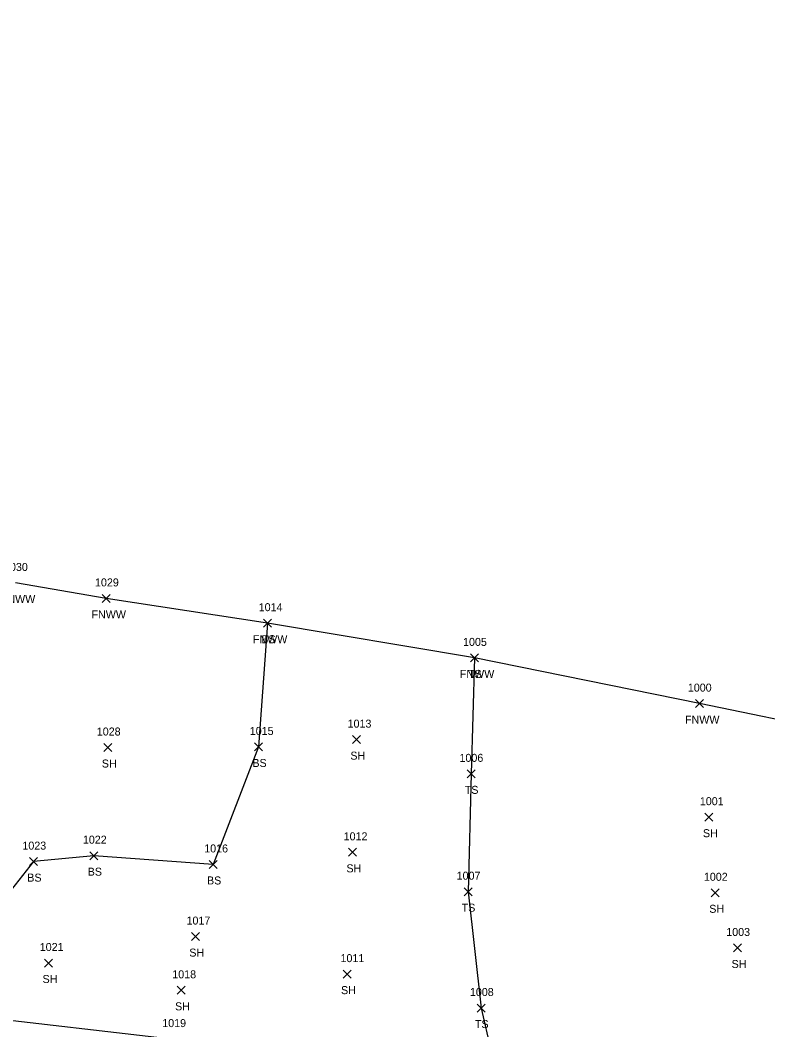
# Model space of a CAD drawing. Extents: x 1629176 to 1637209, y 606063 to 610167.
# Drawn here: x 1629563.1 to 1629750, y 607073 to 607325.3 of the extents above; entities that cross this region are included whole.
import ezdxf

# ---------------------------------------------------------------- set-up
doc = ezdxf.new("R2010")
doc.units = 0
for name, color, linetype in [('L_A', 7, 'Continuous'), ('L_I', 7, 'Continuous'), ('L_TIC', 7, 'Continuous'), ('LELB', 7, 'Continuous'), ('LFNC', 7, 'Continuous')]:
    doc.layers.add(name, color=color, linetype=linetype)

msp = doc.modelspace()

# ---------------------------------------------------------------- linework, layer by layer
at = {"layer": 'L_TIC'}
for points in [[(1629583.57, 607179.8), (1629585.57, 607181.8)], [(1629585.57, 607179.8), (1629583.57, 607181.8)], [(1629623.92, 607173.61), (1629625.92, 607175.61)], [(1629625.92, 607173.61), (1629623.92, 607175.61)], [(1629623.92, 607173.61), (1629625.92, 607175.61)], [(1629625.92, 607173.61), (1629623.92, 607175.61)], [(1629675.65, 607164.93), (1629677.65, 607166.93)], [(1629677.65, 607164.93), (1629675.65, 607166.93)], [(1629675.65, 607164.93), (1629677.65, 607166.93)], [(1629677.65, 607164.93), (1629675.65, 607166.93)], [(1629731.92, 607153.51), (1629733.92, 607155.51)], [(1629733.92, 607153.51), (1629731.92, 607155.51)], [(1629584.01, 607142.54), (1629586.01, 607144.54)], [(1629586.01, 607142.54), (1629584.01, 607144.54)], [(1629621.69, 607142.68), (1629623.69, 607144.68)], [(1629623.69, 607142.68), (1629621.69, 607144.68)], [(1629646.13, 607144.51), (1629648.13, 607146.51)], [(1629648.13, 607144.51), (1629646.13, 607146.51)], [(1629674.81, 607135.96), (1629676.81, 607137.96)], [(1629676.81, 607135.96), (1629674.81, 607137.96)], [(1629734.26, 607125.13), (1629736.26, 607127.13)], [(1629736.26, 607125.13), (1629734.26, 607127.13)], [(1629580.53, 607115.51), (1629582.53, 607117.51)], [(1629582.53, 607115.51), (1629580.53, 607117.51)], [(1629645.16, 607116.35), (1629647.16, 607118.35)], [(1629647.16, 607116.35), (1629645.16, 607118.35)], [(1629565.42, 607114.03), (1629567.42, 607116.03)], [(1629567.42, 607114.03), (1629565.42, 607116.03)], [(1629610.35, 607113.32), (1629612.35, 607115.32)], [(1629612.35, 607113.32), (1629610.35, 607115.32)], [(1629674.04, 607106.51), (1629676.04, 607108.51)], [(1629676.04, 607106.51), (1629674.04, 607108.51)], [(1629735.84, 607106.24), (1629737.84, 607108.24)], [(1629737.84, 607106.24), (1629735.84, 607108.24)], [(1629605.88, 607095.3), (1629607.88, 607097.3)], [(1629607.88, 607095.3), (1629605.88, 607097.3)], [(1629741.43, 607092.45), (1629743.43, 607094.45)], [(1629743.43, 607092.45), (1629741.43, 607094.45)], [(1629569.19, 607088.69), (1629571.19, 607090.69)], [(1629571.19, 607088.69), (1629569.19, 607090.69)], [(1629643.8, 607085.91), (1629645.8, 607087.91)], [(1629645.8, 607085.91), (1629643.8, 607087.91)], [(1629602.31, 607081.87), (1629604.31, 607083.87)], [(1629604.31, 607081.87), (1629602.31, 607083.87)], [(1629677.35, 607077.44), (1629679.35, 607079.44)], [(1629679.35, 607077.44), (1629677.35, 607079.44)]]:
    msp.add_lwpolyline(points, dxfattribs=at)
at = {"layer": 'LELB'}
for points in [[(1629624.92, 607174.61), (1629622.69, 607143.68), (1629611.35, 607114.32), (1629581.53, 607116.51), (1629566.42, 607115.03), (1629550.74, 607095.26), (1629545.75, 607082.85), (1629510.01, 607084.74), (1629471.96, 607087.97), (1629425.24, 607093.21), (1629387.71, 607096.98), (1629341.68, 607100.48), (1629296.79, 607103.99), (1629252.13, 607105.67), (1629240.26, 607107.21), (1629209.02, 607107.58), (1629183.53, 607109.94)], [(1629676.65, 607165.93), (1629675.81, 607136.96), (1629675.04, 607107.51), (1629678.35, 607078.44), (1629683.15, 607057.43)], [(1629683.15, 607057.43), (1629646, 607061.54), (1629600.81, 607070.68), (1629551.82, 607076.32), (1629509.64, 607081.4), (1629471.16, 607085.48), (1629425.18, 607090.24), (1629387.34, 607093.37), (1629341.71, 607096.43), (1629295.02, 607099.94), (1629251.22, 607103.28), (1629239.88, 607103.86), (1629208.74, 607106), (1629183.2, 607107.98)]]:
    msp.add_lwpolyline(points, dxfattribs=at)
at = {"layer": 'LFNC'}
msp.add_lwpolyline([(1629932.18, 607325.29), (1629905.7, 607299.56), (1629894.86, 607289.64), (1629892.4, 607284.76), (1629889.02, 607278.8), (1629873.39, 607261.22), (1629846.96, 607234.11), (1629815.75, 607199.74), (1629791.88, 607173.31), (1629766.82, 607147.57), (1629732.92, 607154.51), (1629676.65, 607165.93), (1629624.92, 607174.61), (1629584.57, 607180.8), (1629561.91, 607184.66)], dxfattribs=at)

# ---------------------------------------------------------------- texts
at = {"layer": 'L_A'}
for s, p in [('FNWW', (1629558.25, 607179.66)), ('FNWW', (1629580.92, 607175.8)), ('FNWW', (1629621.26, 607169.61)), ('BS', (1629623.36, 607169.61)), ('FNWW', (1629672.99, 607160.93)), ('TS', (1629675.05, 607160.93)), ('FNWW', (1629729.27, 607149.51)), ('SH', (1629645.62, 607140.51)), ('SH', (1629583.5, 607138.54)), ('BS', (1629621.13, 607138.68)), ('TS', (1629674.22, 607131.96)), ('SH', (1629733.75, 607121.13)), ('SH', (1629644.64, 607112.35)), ('BS', (1629564.86, 607110.03)), ('BS', (1629579.97, 607111.51)), ('BS', (1629609.79, 607109.32)), ('TS', (1629673.45, 607102.51)), ('SH', (1629735.33, 607102.24)), ('SH', (1629605.36, 607091.3)), ('SH', (1629740.92, 607088.45)), ('SH', (1629568.68, 607084.69)), ('SH', (1629643.29, 607081.91)), ('SH', (1629601.8, 607077.87)), ('TS', (1629676.76, 607073.44))]:
    msp.add_text(s, height=2, dxfattribs=at).set_placement(p)
at = {"layer": 'L_I'}
for s, p in [('1030', (1629559.05, 607187.66)), ('1029', (1629581.79, 607183.8)), ('1014', (1629622.71, 607177.61)), ('1014', (1629622.71, 607177.61)), ('1005', (1629673.79, 607168.93)), ('1005', (1629673.79, 607168.93)), ('1000', (1629729.98, 607157.51)), ('1013', (1629644.93, 607148.51)), ('1028', (1629582.24, 607146.54)), ('1015', (1629620.48, 607146.68)), ('1006', (1629672.9, 607139.96)), ('1001', (1629732.98, 607129.13)), ('1012', (1629643.95, 607120.35)), ('1023', (1629563.64, 607118.03)), ('1022', (1629578.76, 607119.51)), ('1016', (1629609.09, 607117.32)), ('1007', (1629672.19, 607110.51)), ('1002', (1629733.99, 607110.24)), ('1017', (1629604.67, 607099.3)), ('1003', (1629739.58, 607096.45)), ('1021', (1629567.98, 607092.69)), ('1011', (1629643.16, 607089.91)), ('1018', (1629601.11, 607085.87)), ('1008', (1629675.5, 607081.44)), ('1019', (1629598.6, 607073.68))]:
    msp.add_text(s, height=2, dxfattribs=at).set_placement(p)

doc.saveas('drawing.dxf')
